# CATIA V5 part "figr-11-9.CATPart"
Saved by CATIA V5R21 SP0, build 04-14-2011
Part number: Part1
Bounding box of the stored display mesh (mm): x -50 to 50, y -39.834 to 41.856, z -25 to 25
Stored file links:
  D:\CATIA V5R21 E-RESOURCES\CATIA-V5R21\catia-v5r21-prt\c11-catia-v5r21-prt\c11-catia-v5r21-figr-11-9.CATPart
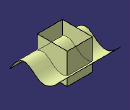
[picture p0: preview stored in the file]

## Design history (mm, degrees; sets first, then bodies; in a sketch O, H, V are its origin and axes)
Set1
  Sketch1 on yz-plane, origin (0, 0, 0), H (0, 1, 0), V (0, 0, 1)
    spline S1 through (-39.8338, -18.0686) (-4.7892, 0) (1.9431, -5.3632) (41.8556, 3.6938)
    point P1 (-4.7892, 0)
    coincidence: P1 H
  Extrude1: Element1 Sketch1, Lim1 50, Lim2 50, Direction yz-plane
  Sketch2 on xy-plane, origin (0, 0, 0), H (1, 0, 0), V (0, 1, 0)
    line L1 (-20.1634, 25.5896) -> (20.7534, 25.5896)
    line L2 (20.7534, 25.5896) -> (20.7534, -23.3463)
    line L3 (20.7534, -23.3463) -> (-20.1634, -23.3463)
    line L4 (-20.1634, -23.3463) -> (-20.1634, 25.5896)
    horizontal: L1 H, L3 H
    vertical: L2 V, L4 V
  Extrude2: Element1 Sketch2, Lim1 25, Lim2 25, Direction xy-plane
  Intersect1: ToIntersect1 Extrude1, ToIntersect2 Extrude2
Body1 (main body)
